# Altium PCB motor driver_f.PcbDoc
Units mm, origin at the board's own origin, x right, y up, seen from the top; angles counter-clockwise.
Board outline 75.69 x 65.41 mm, 2 copper layers (Top Layer, Bottom Layer); 30 components, 26 nets, 120 pads, 0 vias.
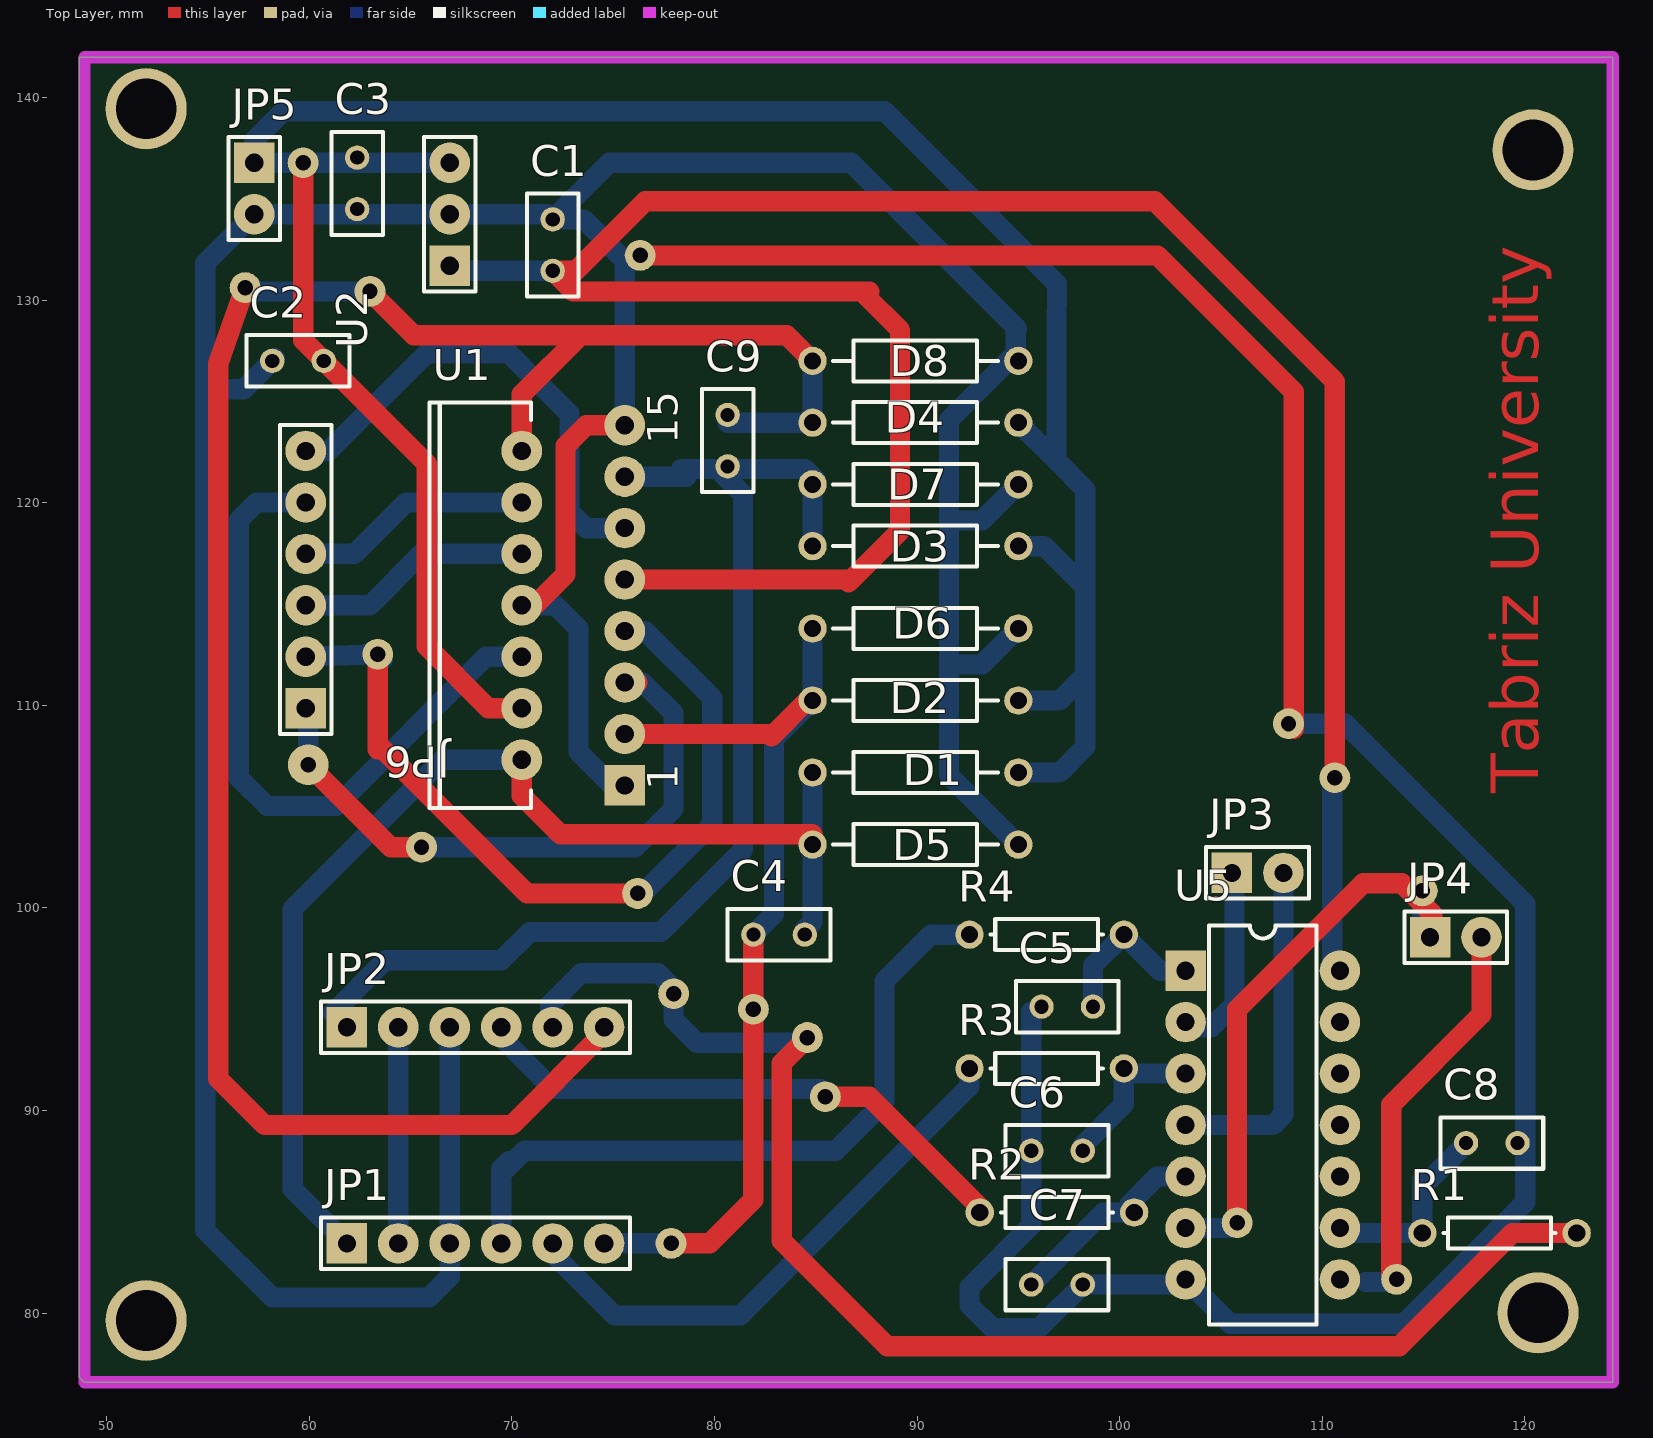
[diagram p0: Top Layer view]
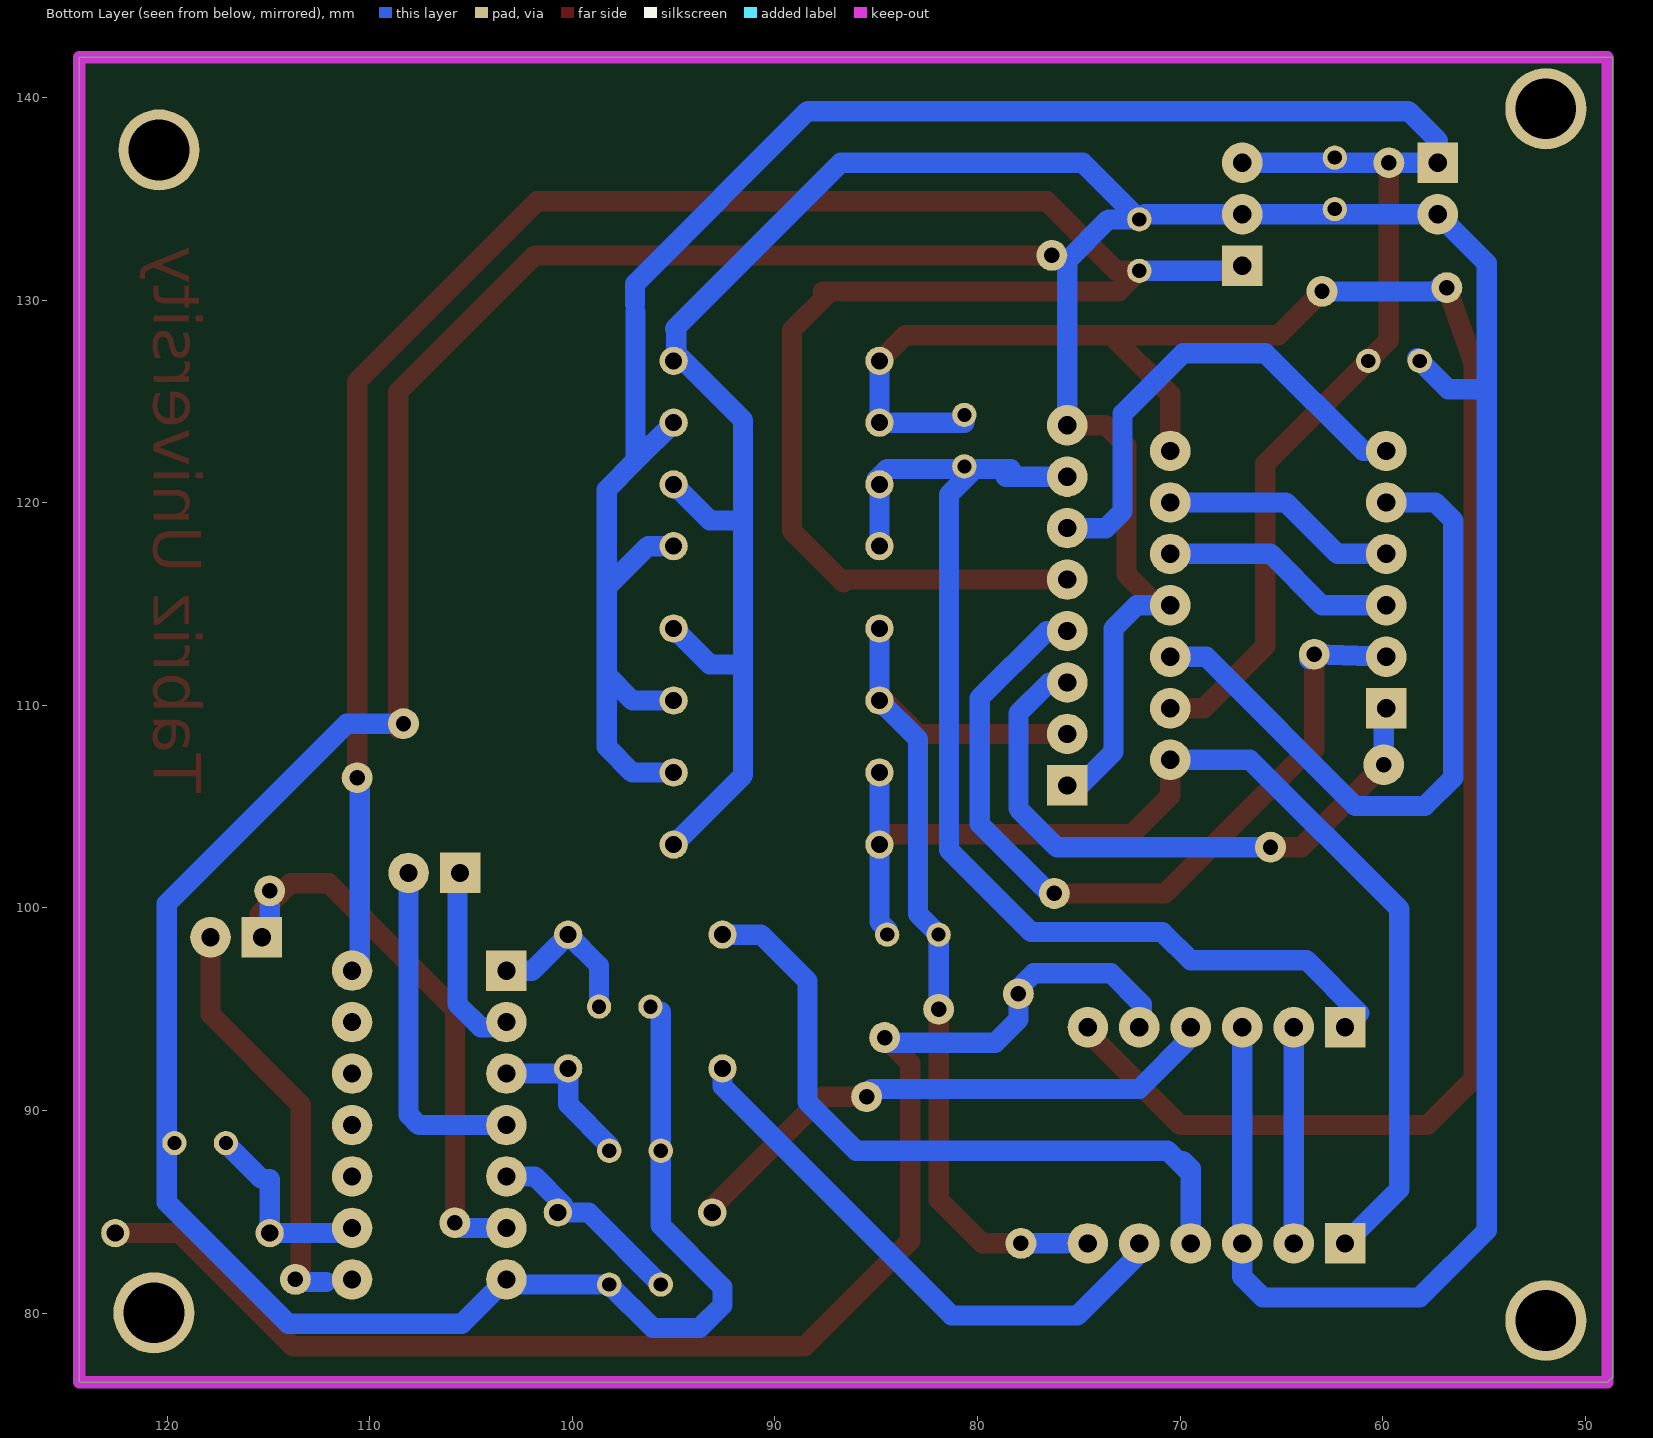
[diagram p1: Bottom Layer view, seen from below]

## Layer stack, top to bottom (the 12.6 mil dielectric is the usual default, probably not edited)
Top Layer: signal copper 0.0356
Dielectric: dielectric 0.32, FR-4, Dk 4.8
Bottom Layer: signal copper 0.0356

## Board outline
48.895,76.581 48.641,76.835 48.641,141.986 124.333,141.986 124.333,76.835 124.333,76.581

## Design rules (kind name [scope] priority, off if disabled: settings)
Clearance [All] p1: gap=0.33
FabricationTestpoint [(IsPad And (OnTopLayer Or OnBottomLayer))] p1: side=3 testpointundercomponent=TRUE minsize=1.016 maxsize=2.54 preferedsize=1.524 minholesize=0 maxholesize=1.016 preferedholesize=0.813 testpointgrid=0.025 allowsidetop=TRUE allowsidebottom=TRUE usegrid=TRUE gridtolerance=0
PolygonConnect [All] p1: connectstyle=Relief reliefconductorwidth=0.254 reliefentries=4 polygonreliefangle="90 Angle"
RoutingVias [All] p1: holewidth=0.813 width=1.575 viastyle="Through Hole" minholewidth=0.711 minwidth=1.27 maxholewidth=0.711 maxwidth=1.27
SilkscreenOverComponentPads [All] p1: minsilkscreentomaskgap=0.254
SolderMaskExpansion [All] p1: expansion=0.102
Width [All] p1: maxlimit=5 minlimit=1 preferedwidth=1.5
26 further rules are at their usual default settings.

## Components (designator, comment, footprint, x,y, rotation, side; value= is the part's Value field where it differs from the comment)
C1 "Cap" RAD-0.1 72.009,132.715 r270 top
C2 "Cap" RAD-0.1 59.436,127 r0 top
C3 "Cap" RAD-0.1 62.357,135.763 r90 top
C4 "Cap" RAD-0.1 83.185,98.679 r0 top
C5 "Cap" RAD-0.1 97.409,95.123 r180 top
C6 "Cap" RAD-0.1 96.901,88.011 r180 top
C7 "Cap" RAD-0.1 96.901,81.407 r0 top
C8 "Cap" RAD-0.1 118.364,88.392 r0 top
C9 "Cap" RAD-0.1 80.645,123.063 r270 top
D1 "Diode" AXIAL-0.4 89.916,106.68 r0 top
D2 "Diode" AXIAL-0.4 89.916,110.236 r0 top
D3 "Diode" AXIAL-0.4 89.916,117.856 r0 top
D4 "Diode" AXIAL-0.4 89.916,123.952 r0 top
D5 "Diode" AXIAL-0.4 89.916,103.124 r180 top
D6 "Diode" AXIAL-0.4 89.916,113.792 r180 top
D7 "Diode" AXIAL-0.4 89.916,120.904 r180 top
D8 "Diode" AXIAL-0.4 89.916,127 r180 top
JP1 "Header 6H" HDR1X6 61.849,83.439 r0 top
JP2 "Header 6H" HDR1X6 61.849,94.107 r0 top
JP3 "Header 2H" HDR1X2 105.537,101.727 r0 top
JP4 "Header 2H" HDR1X2 115.316,98.552 r0 top
JP5 "Header 2H" HDR1X2 57.277,136.779 r270 top
JP6 "Header 6H" HDR1X6 59.817,109.855 r90 top
R1 "Res1" AXIAL-0.3 118.745,83.947 r0 top
R2 "Res1" AXIAL-0.3 96.901,84.963 r180 top
R3 "Res1" AXIAL-0.3 96.393,92.075 r180 top
R4 "Res1" AXIAL-0.3 96.393,98.679 r180 top
U1 "L298N" Multiwatt15V 73.025,114.935 r90 top
U2 "LM109H" HDR1X3 66.929,131.699 r90 top
U5 "MC74HC14AN" 646-06 107.061,89.281 r270 top

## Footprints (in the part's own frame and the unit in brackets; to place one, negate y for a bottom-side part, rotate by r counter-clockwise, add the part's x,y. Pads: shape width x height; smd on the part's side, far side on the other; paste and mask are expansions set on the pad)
646-06 [mm] "DIP; 14 Leads; Row Spacing 7.62 mm; Pitch 2.54 mm"
  rect 2x2 hole 0.9: 1(-7.62,-3.81)
  round 2 hole 0.9: 2(-5.08,-3.81) 3(-2.54,-3.81) 4(0,-3.81) 5(2.54,-3.81) 6(5.08,-3.81) 7(7.62,-3.81) 8(7.62,3.81) 9(5.08,3.81) 10(2.54,3.81) 11(0,3.81) 12(-2.54,3.81) 13(-5.08,3.81) 14(-7.62,3.81)
  silkscreen extent -9.85,-2.65 9.85,2.65
AXIAL-0.3 [mm] "Axial Device, Thru-Hole; 2 Leads; 0.3 in Pin Spacing"
  round 1.4 hole 0.85: 1(-3.81,0) 2(3.81,0)
  silkscreen extent -2.77,-0.76 2.77,0.76
AXIAL-0.4 [mm] "Resistor; 2 Leads"
  round 1.4 hole 0.85: 1(-5.08,0) 2(5.08,0)
  silkscreen extent -4.06,-1.02 4.06,1.02
HDR1X2 [mm] "Connector; Header; 2 Position"
  rect 2x2 hole 0.9: 1(0,0)
  round 2 hole 0.9: 2(2.54,0)
  silkscreen extent -1.27,-1.27 3.81,1.27
HDR1X3 [mm] "Connector; Header; 3 Position"
  rect 2x2 hole 0.9: 1(0,0)
  round 2 hole 0.9: 2(2.54,0) 3(5.08,0)
  silkscreen extent -1.27,-1.27 6.35,1.27
HDR1X6 [mm] "Connector; Header; 6 Position"
  rect 2x2 hole 0.9: 1(0,0)
  round 2 hole 0.9: 2(2.54,0) 3(5.08,0) 4(7.62,0) 5(10.16,0) 6(12.7,0)
  silkscreen extent -1.27,-1.27 13.97,1.27
Multiwatt15V [mm] "TO, Thru-Hole, Vertical, Heatsink Mounted; 15 Bent Staggered Leads; Pitch 1.27 mm"
  rect 2x2 hole 0.9: 1(-8.89,-2.54)
  round 2 hole 0.9: 2(-7.62,2.54) 3(-6.35,-2.54) 4(-5.08,2.54) 5(-3.81,-2.54) 6(-2.54,2.54) 7(-1.27,-2.54) 8(0,2.54) 9(1.27,-2.54) 10(2.54,2.54) 11(3.81,-2.54) 12(5.08,2.54) 13(6.35,-2.54) 14(7.62,2.54) 15(8.89,-2.54)
  silkscreen extent -10,2.09 10,7.09
RAD-0.1 [mm] "Radial Cap, Thru-Hole; 2 Leads; 0.1 in Pin Spacing"
  round 1.2 hole 0.7: 1(-1.27,0) 2(1.27,0)
  silkscreen extent -2.54,-1.27 2.54,1.27

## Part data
C1 C2 C3 C4 C5 C6 C7 C8 C9: "Capacitor"
D1 D2 D3 D4 D5 D6 D7 D8: "Default Diode"
JP1 JP2 JP6: "Header, 6-Pin,  Right Angle"
JP3 JP4 JP5: "Header, 2-Pin,  Right Angle"
R1 R2 R3 R4: "Resistor"
U1: "Dual Full Bridge Driver"
U2: "Monolithic Positive Voltage Regulator"
U5: "Hex Schmitt Trigger Inverter"

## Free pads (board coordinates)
  round 1.524 hole 0.762: 0(76.2,100.711) 1(63.373,112.522) 4(59.69,136.779) 7(65.532,102.997) 8(62.992,130.429) 9(56.828,130.619) 10(110.617,106.426) 11(76.327,132.207) 13(108.331,109.093) 14(77.978,95.758) 15(85.471,90.678) 16(77.851,83.439) 17(81.915,94.996) 18(84.582,93.599) 19(113.665,81.661) 21(114.935,100.838) 23(105.791,84.455)
  round 2 hole 0.762: 2(59.944,107.061)
  round 4 hole 3: 24(51.943,79.629) 24(51.943,139.446) 24(120.396,137.414) 24(120.65,80.01)

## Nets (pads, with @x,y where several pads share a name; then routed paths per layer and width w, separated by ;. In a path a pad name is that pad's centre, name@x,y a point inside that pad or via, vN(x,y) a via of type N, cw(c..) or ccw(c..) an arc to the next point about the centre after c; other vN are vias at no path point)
GND: C1.1 C2.1 C3.1 C5.2 C6.2 C7.2 C8.2 D5.1 D6.1 D7.1 D8.1 JP1.3 JP2.3 JP5.2 pad.11 pad.13 U1.1 U1.8 U1.15 U2.2 U5.7 | length 326.4
  Top Layer w1: U1.8@70.993,114.808 72.644,116.459 72.644,122.809 73.66,123.825 U1.15 ; pad.11 101.854,132.207 108.585,125.476 pad.13@108.585,108.839
  Bottom Layer w1: C2.1@58.293,127.127 56.769,125.603 54.991,125.603 54.864,125.476 ; U2.2@66.675,134.112 66.548,134.239 JP5.2 54.864,131.826 54.864,125.476 ; JP2.3 JP1.3 66.929,81.788 65.913,80.772 58.166,80.772 54.864,84.074 54.864,125.476 ; U2.2 71.755,134.239 C1.1 ; U1.8 72.136,114.935 73.279,113.792 73.279,107.696 74.93,106.045 U1.1 ; U1.15 75.565,131.953 73.533,133.985 C1.1 ; 94.869,128.429 94.869,127.381 91.567,124.079 91.567,119.126 ; 94.932,128.588 86.741,136.779 74.803,136.779 C1.1 ; D5.1 91.567,106.553 91.567,112.014 ; D6.1 93.218,112.014 91.567,112.014 ; D7.1 93.218,119.126 91.567,119.126 ; C5.2@95.631,94.869 C6.2 95.631,84.328 92.583,81.28 92.583,80.391 93.709,79.265 96.029,79.265 C7.2 U5.7@103.124,81.407 ; U5.7 105.443,79.469 114.013,79.469 120.015,85.471 120.015,100.203 111.125,109.093 pad.13 ; 91.567,112.014 91.567,119.126
NetC4_1: C4.1 D2.1 D6.2 JP1.6 pad.16 pad.17 U1.3 | length 51
  Top Layer w1: U1.3 82.931,108.585 ; pad.16 79.756,83.439 81.915,85.598 C4.1 ; 82.804,108.458 D2.1@84.582,110.236
  Bottom Layer w1: JP1.6 pad.16@77.597,83.439 ; pad.17 C4.1 82.931,99.695 82.931,108.331 D2.1 D6.2
NetC4_2: C4.2 D1.1 D5.2 JP1.1 U1.2 | length 57.3
  Top Layer w1: U1.2 70.485,105.537 72.39,103.632 84.836,103.632 D5.2
  Bottom Layer w1: JP1.1 59.182,86.106 59.182,99.949 66.548,107.315 U1.2 ; C4.2@84.455,98.933 84.836,99.314 D5.2 D1.1
NetC5_1: C5.1 R4.1 U5.1 | length 8
  Bottom Layer w1: C5.1 98.679,97.155 R4.1 101.981,96.901 U5.1
NetC6_1: C6.1 R3.1 U5.3 | length 7.8
  Bottom Layer w1: C6.1@98.171,88.265 100.203,90.297 R3.1 100.457,91.821 U5.3
NetC7_1: C7.1 R2.1 U5.5 | length 10.2
  Bottom Layer w1: C7.1 99.187,84.963 R2.1 R2.1@100.711,85.217 ; R2.1@100.457,85.344 101.854,86.741 U5.5
NetC8_1: C8.1 R1.1 U5.9 | length 9.7
  Bottom Layer w1: U5.9 111.125,83.947 R1.1 114.935,86.614 115.316,86.614 C8.1
NetC9_1: C9.1 D4.1 D8.2 JP2.6 pad.8 pad.9 U1.14 | length 104.5
  Top Layer w1: pad.9 55.499,126.873 55.499,91.567 57.785,89.281 69.977,89.281 74.549,93.853 JP2.6 ; pad.8@63.055,130.365 65.151,128.27 73.406,128.27 ; U1.14 70.485,125.349 73.406,128.27 ; 83.566,128.27 73.406,128.27 ; 83.693,128.143 D8.2@84.709,127.127
  Bottom Layer w1: pad.9@57.023,130.81 57.404,130.429 pad.8 ; C9.1@80.645,123.952 D4.1 D8.2
NetC9_2: C9.2 D3.1 D7.2 JP2.1 U1.13 | length 57.1
  Bottom Layer w1: JP2.1 61.151,94.805 63.754,97.409 69.469,97.409 70.866,98.806 77.343,98.806 81.407,102.87 81.407,120.403 80.331,121.479 C9.2@80.518,121.666 ; U1.13 78.613,121.285 ; 78.359,121.666 C9.2@80.518,121.666 ; C9.2 C9.2@80.518,121.666 ; D7.2@84.772,120.968 D7.2 D3.1 ; D7.2@84.963,121.158 84.455,121.666 C9.2@80.518,121.666
NetJP1_4: JP1.4 R4.2 | length 35.5
  Bottom Layer w1: JP1.4 69.469,86.868 ; 69.85,87.503 69.469,87.122 69.469,86.868 ; 88.392,96.139 88.392,90.424 85.979,88.011 70.612,88.011 69.469,86.868 ; 88.392,96.393 90.678,98.679 R4.2
NetJP1_5: JP1.5 R3.2 | length 27.9
  Bottom Layer w1: JP1.5 72.009,82.931 75.057,79.883 81.28,79.883 92.583,91.186 R3.2
NetJP2_4: JP2.4 pad.15 R2.2 | length 27
  Top Layer w1: pad.15 87.63,90.678 R2.2@93.091,85.217
  Bottom Layer w1: JP2.4@69.342,93.726 72.009,91.059 85.217,91.059 pad.15@85.344,90.932
NetJP2_5: JP2.5 pad.14 pad.18 R1.2 | length 70.4
  Top Layer w1: pad.18 83.312,92.329 83.312,83.566 88.519,78.359 113.792,78.359 119.38,83.947 R1.2
  Bottom Layer w1: JP2.5@71.882,94.361 71.882,95.25 73.406,96.774 77.216,96.774 pad.14@77.851,96.139 ; pad.14 77.978,94.488 79.121,93.345 pad.18@84.582,93.345
NetJP3_1: JP3.1 U5.2 | length 9.3
  Bottom Layer w1: U5.2@103.378,94.107 104.521,94.107 105.664,95.25 105.664,101.6 JP3.1
NetJP3_2: JP3.2 U5.4 | length 17
  Bottom Layer w1: U5.4 107.569,89.281 108.077,89.789 JP3.2
NetJP4_1: JP4.1 pad.21 pad.23 U5.6 | length 29.6
  Top Layer w1: pad.23 105.791,94.996 112.014,101.219 113.919,101.219 115.443,99.695 JP4.1@115.443,98.552
  Bottom Layer w1: U5.6 105.537,84.201 pad.23 ; pad.21 114.935,98.933 JP4.1
NetJP4_2: JP4.2 pad.19 U5.8 | length 19.8
  Top Layer w1: pad.19 113.405,81.921 113.405,90.291 117.856,94.742 JP4.2
  Bottom Layer w1: 112.141,81.534 pad.19@113.089,81.534
NetJP6_1: JP6.1 pad.2 pad.7 U1.5 | length 31.7
  Top Layer w1: pad.2 64.008,102.997 pad.7 ; U1.5 U1.5@76.2,111.125
  Bottom Layer w1: JP6.1 59.944,109.728 pad.2 ; pad.7 76.073,102.997 77.978,104.902 77.978,109.601 76.454,111.125 U1.5
NetJP6_2: JP6.2 pad.0 pad.1 U1.7 | length 40.9
  Top Layer w1: 63.373,107.823 pad.1 ; 63.373,108.077 70.739,100.711 pad.0
  Bottom Layer w1: JP6.2 pad.1 pad.1@63.627,112.268 ; U1.7 76.581,113.665 79.883,110.363 79.883,104.14 pad.0@76.708,100.965
NetJP6_3: JP6.3 U1.10 | length 11.7
  Bottom Layer w1: JP6.3 62.992,114.935 65.532,117.475 U1.10
NetJP6_4: JP6.4 U1.12 | length 11.7
  Bottom Layer w1: JP6.4 62.23,117.475 64.77,120.015 U1.12
NetJP6_5: JP6.5 U1.6 | length 34
  Bottom Layer w1: JP6.5 57.404,120.015 56.515,119.126 56.515,106.426 57.912,105.029 61.341,105.029 68.707,112.395 U1.6
NetJP6_6: JP6.6 U1.11 | length 24.2
  Bottom Layer w1: JP6.6 60.96,122.555 65.786,127.381 69.85,127.381 72.833,124.398 72.833,119.572 73.66,118.745 U1.11
VCC: JP1.2 JP2.2 | length 10.7
  Bottom Layer w1: JP1.2 JP2.2
VDD: C1.2 pad.10 U1.9 U2.1 U5.14 | length 121.7
  Top Layer w1: U1.9 86.741,116.205 ; 86.614,116.078 89.154,118.618 89.154,128.524 87.376,130.302 ; 87.63,130.429 73.025,130.429 C1.2 73.152,131.445 76.581,134.874 101.727,134.874 110.617,125.984 pad.10@110.617,106.172
  Bottom Layer w1: U2.1@66.802,131.445 C1.2 ; U5.14@110.49,96.774 110.49,106.299 pad.10
VIN: C2.2 C3.2 D1.2 D2.2 D3.2 D4.2 JP5.1 pad.4 U1.4 U2.3 | length 124.4
  Top Layer w1: pad.4 59.69,128.016 65.786,121.92 65.786,112.903 68.834,109.855 U1.4
  Bottom Layer w1: U2.3 pad.4 JP5.1 57.277,137.881 58.715,139.319 88.392,139.319 96.901,130.81 96.901,129.794 ; D1.2 97.028,106.68 98.298,107.95 98.298,111.506 ; D2.2 97.028,110.236 98.298,111.506 ; D3.2 96.266,117.856 98.298,115.824 ; D4.2 96.881,122.067 ; 96.881,129.433 96.881,122.067 ; 96.881,122.067 98.298,120.65 98.298,115.824 ; 98.298,111.506 98.298,115.824
pads on no net: U5.10 U5.11 U5.12 U5.13

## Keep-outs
Keep-Out Layer:
  lines w0.6: 48.895,76.581 48.895,141.986 124.333,141.986 124.333,76.581 48.895,76.581

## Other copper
Top Layer:
  text "Tabriz University" at 121.412,105.664 h4 r90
